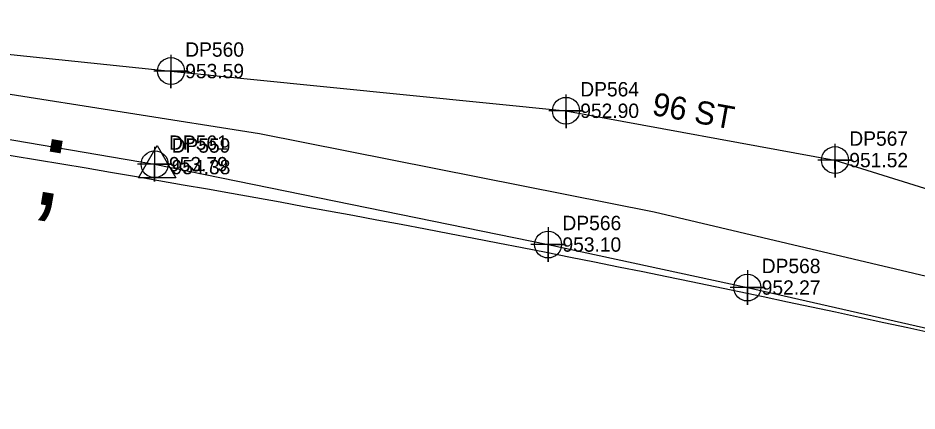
# Model space of a CAD drawing. Extents: x 1182322 to 1186765, y 572295 to 575411.
# Drawn here: x 1185441.1 to 1185597.5, y 573652.7 to 573721.1 of the extents above; entities that cross this region are included whole.
import ezdxf

# ---------------------------------------------------------------- set-up
doc = ezdxf.new("R2010")
doc.units = 0
for name, color, linetype in [('Exist Other Culture Fence Line', 7, 'Continuous'), ('Exist Other Culture Fence Line Cogo Elevation', 7, 'Continuous'), ('Exist Other Culture Fence Line Cogo Number', 7, 'Continuous'), ('Exist Other Culture Fence Line Cogo Point CELL', 7, 'Continuous'), ('Exist Right of Way Control of Access CA Symbol CELL', 7, 'Continuous'), ('Exist Right of Way Line', 7, 'Continuous'), ('Exist Right of Way Monument CELL', 7, 'Continuous'), ('Exist Right of Way Monument Cogo Elevation', 7, 'Continuous'), ('Exist Right of Way Monument Cogo Number', 7, 'Continuous'), ('Exist Utilities Telephone UG Conduit SUE LOS B', 7, 'Continuous'), ('Exist Utilities Telephone UG Conduit SUE LOS B Cogo Elevation', 7, 'Continuous'), ('Exist Utilities Telephone UG Conduit SUE LOS B Cogo Number', 7, 'Continuous'), ('Exist Utilities Telephone UG Conduit SUE LOS B Cogo Point CELL', 7, 'Continuous'), ('Exist Utilities Telephone UG Conduit SUE LOS B Text', 7, 'Continuous'), ('Sheet Layout Plan Border', 7, 'Continuous')]:
    doc.layers.add(name, color=color, linetype=linetype)

msp = doc.modelspace()

# ---------------------------------------------------------------- linework, layer by layer
at = {"layer": 'Exist Other Culture Fence Line'}
msp.add_lwpolyline([(1184699.34, 573697.51), (1184773.78, 573703.02), (1184848.65, 573709.06), (1184900.84, 573713.11), (1184965.64, 573718.36), (1185023.1, 573721.56), (1185061.74, 573723.1), (1185125.69, 573725.08), (1185204.48, 573724.02), (1185248.27, 573721.81), (1185300.17, 573718.11), (1185350.66, 573712.74), (1185422.95, 573702.8), (1185464.84, 573695.68), (1185533.29, 573681.7), (1185567.96, 573674.22), (1185634.32, 573659.17)], dxfattribs=at)
at = {"layer": 'Exist Other Culture Fence Line Cogo Point CELL'}
for points in [[(1185464.84, 573698.68), (1185464.84, 573692.68), (1185464.84, 573695.68), (1185467.84, 573695.68), (1185461.84, 573695.68)], [(1185533.29, 573684.7), (1185533.29, 573678.7), (1185533.29, 573681.7), (1185536.29, 573681.7), (1185530.29, 573681.7)], [(1185567.96, 573677.22), (1185567.96, 573671.22), (1185567.96, 573674.22), (1185570.96, 573674.22), (1185564.96, 573674.22)]]:
    msp.add_lwpolyline(points, dxfattribs=at)
for centre in [(1185464.84, 573695.68), (1185533.29, 573681.7), (1185567.96, 573674.22)]:
    msp.add_circle(centre, 2.34, dxfattribs=at)
at = {"layer": 'Exist Right of Way Control of Access CA Symbol CELL'}
msp.add_line((1185451.85, 573695.14), (1185451.85, 573695.14), dxfattribs=at)
at = {"layer": 'Exist Right of Way Line'}
msp.add_arc((1184948.77, 570719.25), 3018.12, 76.39941, 81.6044, dxfattribs=at)
at = {"layer": 'Exist Right of Way Monument CELL'}
msp.add_line((1185465.29, 573695.18), (1185465.29, 573695.18), dxfattribs=at)
msp.add_lwpolyline([(1185462.04, 573693.29), (1185465.29, 573698.93), (1185468.54, 573693.29)], close=True, dxfattribs=at)
at = {"layer": 'Exist Utilities Telephone UG Conduit SUE LOS B'}
msp.add_lwpolyline([(1184705.2, 573717.51), (1184761.61, 573719.92), (1184808.75, 573719.14), (1184855.63, 573717.48), (1184899.38, 573717.73), (1184947.65, 573726.76), (1184989.59, 573731.99), (1185049.6, 573740.86), (1185104.23, 573742.11), (1185147.54, 573741.49), (1185190.99, 573738.17), (1185243.67, 573733.83), (1185296.19, 573730.81), (1185343.76, 573727.54), (1185391.61, 573722.1), (1185423.08, 573716.53), (1185467.66, 573711.88), (1185536.39, 573704.97), (1185583.2, 573696.39), (1185626.44, 573682.88)], dxfattribs=at)
at = {"layer": 'Exist Utilities Telephone UG Conduit SUE LOS B Cogo Point CELL'}
for points in [[(1185467.65, 573714.69), (1185467.68, 573708.88), (1185467.66, 573711.88), (1185470.68, 573711.88), (1185464.68, 573711.88)], [(1185536.38, 573707.78), (1185536.41, 573701.97), (1185536.39, 573704.97), (1185539.41, 573704.97), (1185533.41, 573704.97)], [(1185583.19, 573699.2), (1185583.22, 573693.39), (1185583.2, 573696.39), (1185586.22, 573696.39), (1185580.22, 573696.39)]]:
    msp.add_lwpolyline(points, dxfattribs=at)
for centre in [(1185467.68, 573711.88), (1185536.41, 573704.97), (1185583.22, 573696.39)]:
    msp.add_circle(centre, 2.34, dxfattribs=at)
at = {"layer": 'Sheet Layout Plan Border'}
for p, q in [((1185483.06, 573700.95), (1185411.32, 573712.28)), ((1185551.77, 573687.35), (1185483.06, 573700.95)), ((1185625.02, 573669.98), (1185551.77, 573687.35))]:
    msp.add_line(p, q, dxfattribs=at)

# ---------------------------------------------------------------- texts
at = {"layer": 'Exist Other Culture Fence Line Cogo Elevation'}
for s, p in [('953.79', (1185467.34, 573694.43)), ('953.10', (1185535.79, 573680.45)), ('952.27', (1185570.46, 573672.97))]:
    msp.add_text(s, height=2.5, dxfattribs=at).set_placement(p)
at = {"layer": 'Exist Other Culture Fence Line Cogo Number'}
for s, p in [('DP561', (1185467.34, 573698.18)), ('DP566', (1185535.79, 573684.2)), ('DP568', (1185570.46, 573676.72))]:
    msp.add_text(s, height=2.5, dxfattribs=at).set_placement(p)
at = {"layer": 'Exist Right of Way Control of Access CA Symbol CELL'}
msp.add_text(';', height=15, rotation=350.4047, dxfattribs=at).set_placement((1185443.2, 573689))
at = {"layer": 'Exist Right of Way Monument Cogo Elevation'}
msp.add_text('954.38', height=2.5, dxfattribs=at).set_placement((1185467.79, 573693.93))
at = {"layer": 'Exist Right of Way Monument Cogo Number'}
msp.add_text('DP559', height=2.5, dxfattribs=at).set_placement((1185467.79, 573697.68))
at = {"layer": 'Exist Utilities Telephone UG Conduit SUE LOS B Cogo Elevation'}
for s, p in [('953.59', (1185470.16, 573710.63)), ('952.90', (1185538.89, 573703.72)), ('951.52', (1185585.7, 573695.14))]:
    msp.add_text(s, height=2.5, dxfattribs=at).set_placement(p)
at = {"layer": 'Exist Utilities Telephone UG Conduit SUE LOS B Cogo Number'}
for s, p in [('DP560', (1185470.16, 573714.38)), ('DP564', (1185538.89, 573707.47)), ('DP567', (1185585.7, 573698.89))]:
    msp.add_text(s, height=2.5, dxfattribs=at).set_placement(p)
at = {"layer": 'Exist Utilities Telephone UG Conduit SUE LOS B Text'}
msp.add_text('96 ST', height=4, rotation=349.6124, dxfattribs=at).set_placement((1185551.21, 573704.28))

doc.saveas('drawing.dxf')
